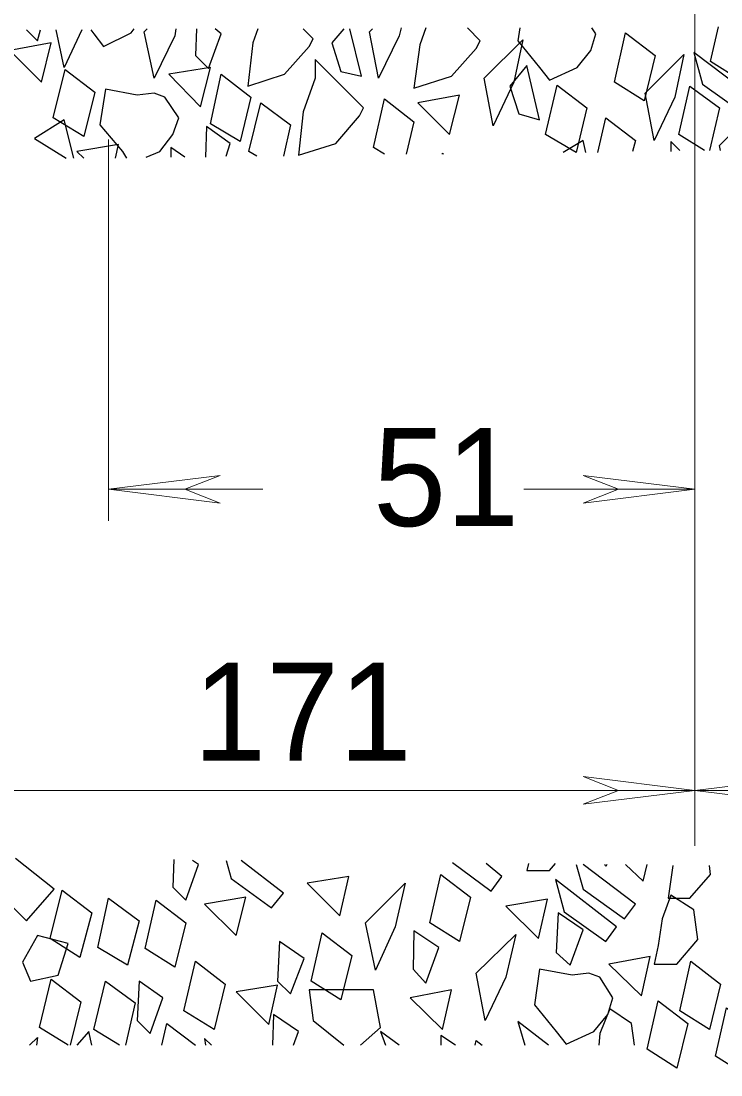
# Model space of a CAD drawing. Extents: x 312583 to 312854, y 144419 to 144597.
# Drawn here: x 312698.24 to 312703.67, y 144443.42 to 144451.6 of the extents above; entities that cross this region are included whole.
import ezdxf

# ---------------------------------------------------------------- set-up
doc = ezdxf.new("R2010")
doc.units = 0
doc.header["$LTSCALE"] = 0.3
doc.layers.add('1', color=7, linetype='Continuous', lineweight=25)
doc.layers.add('2', color=7, linetype='Continuous', lineweight=13)

msp = doc.modelspace()

# ---------------------------------------------------------------- linework, layer by layer
at = {"layer": '1'}
for p, q in [((312698.7797, 144451.531), (312698.8027, 144451.5004)), ((312699.1937, 144451.5157), (312699.2167, 144451.5387)), ((312700.7424, 144451.5387), (312700.6504, 144451.4314)), ((312700.9417, 144451.5157), (312700.9647, 144451.5387)), ((312703.5867, 144451.2857), (312703.648, 144451.554)), ((312699.6767, 144450.7797), (312699.669, 144450.542)), ((312703.5407, 144450.5957), (312703.3414, 144450.7184)), ((312698.3427, 144450.6877), (312698.588, 144450.5344)), ((312703.6634, 144450.5957), (312703.6557, 144450.634)), ((312698.6724, 144450.588), (312698.726, 144450.5344)), ((312699.025, 144450.588), (312699.0557, 144450.5344)), ((312699.4007, 144450.6187), (312699.4007, 144450.542)), ((312699.508, 144450.542), (312699.4007, 144450.6187)), ((312700.0677, 144450.5497), (312700.0064, 144450.588)), ((312701.0567, 144450.565), (312700.9724, 144450.6187)), ((312699.83, 144445.0834), (312699.8684, 144444.9454)), ((312702.544, 144445.0527), (312702.5977, 144444.861)), ((312700.198, 144443.8874), (312700.1904, 144443.6497)), ((312700.5047, 144443.8414), (312700.7424, 144443.6497)), ((312698.6034, 144443.6497), (312698.381, 144443.7877)), ((312699.002, 144443.6497), (312698.8027, 144443.7724)), ((312701.4937, 144443.7264), (312701.4937, 144443.6497)), ((312701.6087, 144443.6497), (312701.4937, 144443.7264))]:
    msp.add_line(p, q, dxfattribs=at)
for points in [[(312698.2814, 144451.531), (312698.3657, 144451.4467), (312698.3887, 144451.531)], [(312698.7107, 144451.531), (312698.5727, 144451.2397), (312698.5114, 144451.531)], [(312698.8027, 144451.5004), (312698.8794, 144451.4007), (312699.094, 144451.508), (312699.117, 144451.5387)], [(312699.439, 144451.5387), (312699.4314, 144451.485), (312699.2704, 144451.1554), (312699.1937, 144451.5157)], [(312699.6, 144451.5387), (312699.5924, 144451.3317), (312699.692, 144451.232), (312699.7917, 144451.5004), (312699.7457, 144451.5387)], [(312700.0754, 144451.5387), (312700.037, 144451.4314), (312699.9987, 144451.094), (312700.2824, 144451.186), (312700.474, 144451.4007), (312700.5047, 144451.462), (312700.428, 144451.5387)], [(312700.6504, 144451.4314), (312700.7194, 144451.209), (312700.8804, 144451.1707), (312700.7884, 144451.5387)], [(312701.187, 144451.5464), (312701.1717, 144451.485), (312701.0107, 144451.1554), (312700.9417, 144451.5157)], [(312701.3787, 144451.5464), (312701.3327, 144451.416), (312701.2867, 144451.0787), (312701.578, 144451.1707), (312701.7697, 144451.3854), (312701.8004, 144451.4467), (312701.7007, 144451.5464)], [(312702.107, 144451.5464), (312702.0917, 144451.4467), (312702.2604, 144451.2397)], [(312702.2604, 144451.2397), (312702.337, 144451.14), (312702.5517, 144451.2397), (312702.659, 144451.37), (312702.6974, 144451.5004), (312702.6667, 144451.5464)], [(312703.8167, 144451.554), (312703.9087, 144451.4927), (312703.8167, 144451.14), (312703.5867, 144451.2857)], [(312699.209, 144450.542), (312699.3164, 144450.588), (312699.416, 144450.7184), (312699.462, 144450.8487), (312699.3547, 144451.0097), (312699.2704, 144451.0404), (312699.14, 144451.025), (312698.8947, 144451.071), (312698.8487, 144450.795), (312699.025, 144450.588)], [(312703.3414, 144450.7184), (312703.4257, 144451.094), (312703.6557, 144450.9254), (312703.579, 144450.5957)], [(312700.0064, 144450.588), (312700.0984, 144450.9637), (312700.3284, 144450.795), (312700.2747, 144450.5497)], [(312700.9724, 144450.6187), (312701.0567, 144450.9944), (312701.2867, 144450.818), (312701.2254, 144450.565)], [(312703.6557, 144450.634), (312703.9624, 144450.933), (312703.8934, 144450.6034), (312703.8857, 144450.5957)], [(312698.6494, 144450.5344), (312698.5727, 144450.8334), (312698.3427, 144450.6877)], [(312702.7127, 144450.5804), (312702.774, 144450.8487), (312703.004, 144450.6724), (312702.981, 144450.588)], [(312699.83, 144450.5497), (312699.8607, 144450.6494), (312699.6767, 144450.7797)], [(312698.9714, 144450.5344), (312698.9944, 144450.6417), (312698.6724, 144450.588)], [(312702.6207, 144450.5804), (312702.5977, 144450.6724), (312702.4444, 144450.5804)], [(312703.349, 144450.5957), (312703.28, 144450.6647), (312703.28, 144450.588)], [(312701.509, 144450.565), (312701.509, 144450.5727), (312701.5167, 144450.565)], [(312697.9977, 144445.1064), (312697.9057, 144444.9914), (312698.2814, 144444.6157), (312698.496, 144444.861), (312698.197, 144445.0987)], [(312699.4237, 144445.091), (312699.416, 144444.8764), (312699.5157, 144444.7767), (312699.6154, 144445.0527), (312699.5694, 144445.0834)], [(312699.8684, 144444.9454), (312700.1827, 144444.7154), (312700.2747, 144444.8304), (312699.945, 144445.0834)], [(312701.5857, 144445.068), (312701.8847, 144444.8457), (312701.969, 144444.9607), (312701.8464, 144445.0604)], [(312702.176, 144445.0604), (312702.1607, 144445.0067), (312702.337, 144445.0067), (312702.383, 144445.0604)], [(312702.5977, 144444.861), (312702.9197, 144444.631), (312703.004, 144444.746), (312702.5977, 144445.0527)], [(312702.7817, 144445.0527), (312702.774, 144445.0374), (312702.7664, 144445.0527)], [(312702.9274, 144445.0527), (312703.0654, 144444.9224), (312703.096, 144445.0527)], [(312703.2954, 144445.045), (312703.28, 144444.9377), (312703.257, 144444.792), (312703.4257, 144444.792), (312703.5867, 144444.976), (312703.579, 144445.045)], [(312698.381, 144443.7877), (312698.473, 144444.1634), (312698.703, 144443.987), (312698.6187, 144443.6497)], [(312698.8027, 144443.7724), (312698.8947, 144444.148), (312699.1247, 144443.9794), (312699.048, 144443.6497)], [(312700.8727, 144443.6497), (312701.026, 144443.7877), (312700.9724, 144444.079), (312700.474, 144444.079), (312700.5047, 144443.8414)], [(312702.8047, 144443.9334), (312702.728, 144443.7417), (312702.7204, 144443.6497)], [(312702.9964, 144443.6497), (312702.9734, 144443.8184), (312702.8047, 144443.9334)], [(312700.3514, 144443.6497), (312700.3897, 144443.757), (312700.198, 144443.8874)], [(312698.7874, 144443.6497), (312698.7644, 144443.757), (312698.6724, 144443.6497)], [(312699.3317, 144443.6497), (312699.37, 144443.8184), (312699.5924, 144443.6497)], [(312701.1717, 144443.6497), (312701.026, 144443.757), (312701.0644, 144443.6497)], [(312702.3294, 144443.6497), (312702.0917, 144443.8337), (312702.1454, 144443.6497)], [(312698.3044, 144443.6497), (312698.3657, 144443.711), (312698.358, 144443.6497)], [(312699.715, 144443.6497), (312699.6614, 144443.7034), (312699.669, 144443.6497)], [(312701.762, 144443.6497), (312701.7697, 144443.688), (312701.8157, 144443.6497)]]:
    msp.add_lwpolyline(points, dxfattribs=at)
for points in [[(312701.831, 144451.1554), (312702.13, 144451.4544), (312702.061, 144451.1247), (312701.9, 144450.7874)], [(312702.843, 144451.1247), (312702.9274, 144451.508), (312703.1574, 144451.3317), (312703.073, 144450.979)], [(312698.151, 144451.37), (312698.3964, 144451.1247), (312698.473, 144451.4314)], [(312700.52, 144451.1554), (312700.428, 144450.8947), (312700.3897, 144450.5574), (312700.681, 144450.6494), (312700.865, 144450.864), (312700.8957, 144450.9254), (312700.52, 144451.301)], [(312703.0807, 144451.0404), (312703.3797, 144451.3394), (312703.3107, 144451.0097), (312703.1497, 144450.6724)], [(312703.5254, 144451.1094), (312703.8474, 144450.8794), (312703.9317, 144450.9944), (312703.4564, 144451.3547)], [(312698.4884, 144450.8487), (312698.5804, 144451.2244), (312698.8104, 144451.048), (312698.726, 144450.703)], [(312699.3854, 144451.186), (312699.6307, 144450.933), (312699.7074, 144451.2397)], [(312702.0304, 144451.094), (312702.0994, 144450.8794), (312702.2604, 144450.8334), (312702.1607, 144451.255)], [(312699.7074, 144450.8027), (312699.7917, 144451.186), (312700.0217, 144451.0097), (312699.9374, 144450.6647)], [(312702.3064, 144450.7184), (312702.3984, 144451.1017), (312702.6284, 144450.9254), (312702.544, 144450.5804)], [(312701.3174, 144450.9637), (312701.5627, 144450.7184), (312701.6394, 144451.025)], [(312700.4587, 144444.907), (312700.7117, 144444.654), (312700.7807, 144444.9607)], [(312700.911, 144444.6004), (312701.2177, 144444.907), (312701.141, 144444.5697), (312700.9877, 144444.2324)], [(312701.4094, 144444.6004), (312701.4937, 144444.976), (312701.7237, 144444.7997), (312701.6394, 144444.4547)], [(312702.452, 144444.6847), (312702.774, 144444.4547), (312702.8584, 144444.5697), (312702.383, 144444.9377)], [(312698.4654, 144444.4777), (312698.5574, 144444.8534), (312698.7874, 144444.677), (312698.6954, 144444.332)], [(312698.8334, 144444.4087), (312698.9177, 144444.792), (312699.1554, 144444.6157), (312699.0634, 144444.2707)], [(312699.2014, 144444.401), (312699.2857, 144444.7767), (312699.5157, 144444.6004), (312699.4314, 144444.2554)], [(312699.6614, 144444.746), (312699.9067, 144444.5007), (312699.9834, 144444.7997)], [(312701.9997, 144444.7307), (312702.2527, 144444.4777), (312702.3217, 144444.7844)], [(312703.28, 144444.815), (312703.211, 144444.631), (312703.1804, 144444.424), (312703.1497, 144444.2784), (312703.326, 144444.2784), (312703.487, 144444.47), (312703.4564, 144444.7)], [(312702.406, 144444.677), (312702.3907, 144444.3704), (312702.498, 144444.2707), (312702.5977, 144444.5467)], [(312698.3657, 144444.5007), (312698.2507, 144444.2937), (312698.312, 144444.148), (312698.5267, 144444.194), (312698.6034, 144444.4394)], [(312700.4894, 144444.148), (312700.5737, 144444.5237), (312700.8037, 144444.3474), (312700.7194, 144444.0024)], [(312701.2867, 144444.539), (312701.279, 144444.24), (312701.3787, 144444.1327), (312701.4784, 144444.4087)], [(312701.7697, 144444.2094), (312702.0764, 144444.5084), (312701.9997, 144444.1787), (312701.8387, 144443.8414)], [(312700.244, 144444.4547), (312700.2287, 144444.148), (312700.3284, 144444.0484), (312700.4357, 144444.3244)], [(312702.797, 144444.2784), (312703.05, 144444.033), (312703.119, 144444.3397)], [(312699.5004, 144443.918), (312699.5924, 144444.3014), (312699.8224, 144444.125), (312699.738, 144443.7724)], [(312703.349, 144443.918), (312703.4334, 144444.3014), (312703.6634, 144444.125), (312703.579, 144443.7724)], [(312702.3907, 144443.757), (312702.4674, 144443.6574), (312702.682, 144443.757), (312702.7894, 144443.8874), (312702.8277, 144444.0177), (312702.728, 144444.1787), (312702.6437, 144444.2094), (312702.5134, 144444.194), (312702.2604, 144444.24), (312702.222, 144443.964)], [(312699.1554, 144444.148), (312699.14, 144443.8414), (312699.2397, 144443.7417), (312699.3394, 144444.0177)], [(312699.9067, 144444.0637), (312700.1597, 144443.8107), (312700.2287, 144444.1174)], [(312701.256, 144444.0177), (312701.509, 144443.7724), (312701.578, 144444.079)], [(312703.096, 144443.619), (312703.1804, 144443.9947), (312703.4104, 144443.8184), (312703.326, 144443.4734)], [(312703.625, 144443.5654), (312703.7094, 144443.941), (312703.9394, 144443.7724), (312703.855, 144443.4197)]]:
    msp.add_lwpolyline(points, close=True, dxfattribs=at)
at = {"layer": '2'}
for p, q in [((312703.464, 144456.706), (312703.464, 144445.1984)), ((312698.9177, 144450.68), (312698.9177, 144447.7207)), ((312698.9177, 144447.966), (312699.784, 144448.0734)), ((312699.784, 144448.0734), (312699.508, 144447.966)), ((312702.5977, 144448.0734), (312702.8737, 144447.966)), ((312703.464, 144447.966), (312702.5977, 144448.0734)), ((312700.1137, 144447.966), (312698.9177, 144447.966)), ((312698.9177, 144447.966), (312699.784, 144447.8587)), ((312699.784, 144447.8587), (312699.508, 144447.966)), ((312703.464, 144447.966), (312702.1377, 144447.966)), ((312702.5977, 144447.8587), (312702.8737, 144447.966)), ((312703.464, 144447.966), (312702.5977, 144447.8587)), ((312702.5977, 144445.735), (312702.8737, 144445.6277)), ((312703.464, 144445.6277), (312702.5977, 144445.735)), ((312703.464, 144445.6277), (312704.3304, 144445.735)), ((312697.001, 144445.6277), (312703.464, 144445.6277)), ((312702.5977, 144445.5204), (312702.8737, 144445.6277)), ((312703.464, 144445.6277), (312702.5977, 144445.5204)), ((312703.464, 144445.6277), (312719.2804, 144445.6277)), ((312703.464, 144445.6277), (312704.3304, 144445.5204))]:
    msp.add_line(p, q, dxfattribs=at)

# ---------------------------------------------------------------- texts
for s, p in [('51 ', (312700.9704, 144447.6799)), ('171 ', (312699.5747, 144445.8596))]:
    msp.add_text(s, height=0.76, dxfattribs=at).set_placement(p)

doc.saveas('drawing.dxf')
